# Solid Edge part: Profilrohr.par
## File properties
Username: bmolnar
Dokumentum tartalom típus: 0
Author: bmolnar
Last saved by: bmolnar
Revision: 79
Sűrűség: 0,000 kg/m^3
Pontosság: 0,990
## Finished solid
Body 1: solid body, 115 faces, 338 edges, 224 vertices.
  Faces by surface: cylinder 59, plane 56
  Edges by curve: line 220, circle 118
Bounding box of the edges (mm): 95.500 x 95.500 x 44.000, from (-47.75, -47.75, -15) to (47.75, 47.75, 29).
Cylindrical faces by radius (mm): R0.2 x24, R0.5 x24, R1 x4, R10 x4, R13.5 x2, R40 x1
Planar faces by outward normal: +x 13, +y 14, +z 1, -x 13, -y 14, -z 1
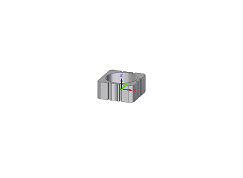
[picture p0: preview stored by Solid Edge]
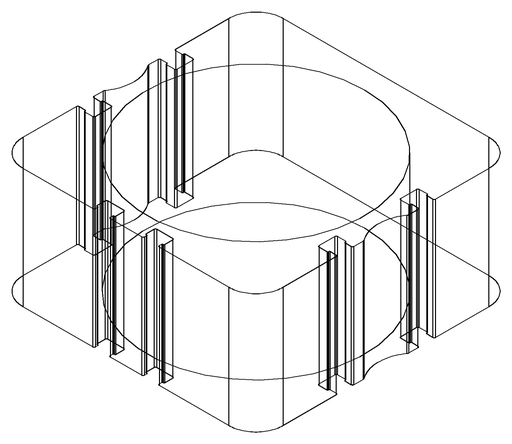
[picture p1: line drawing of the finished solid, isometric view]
